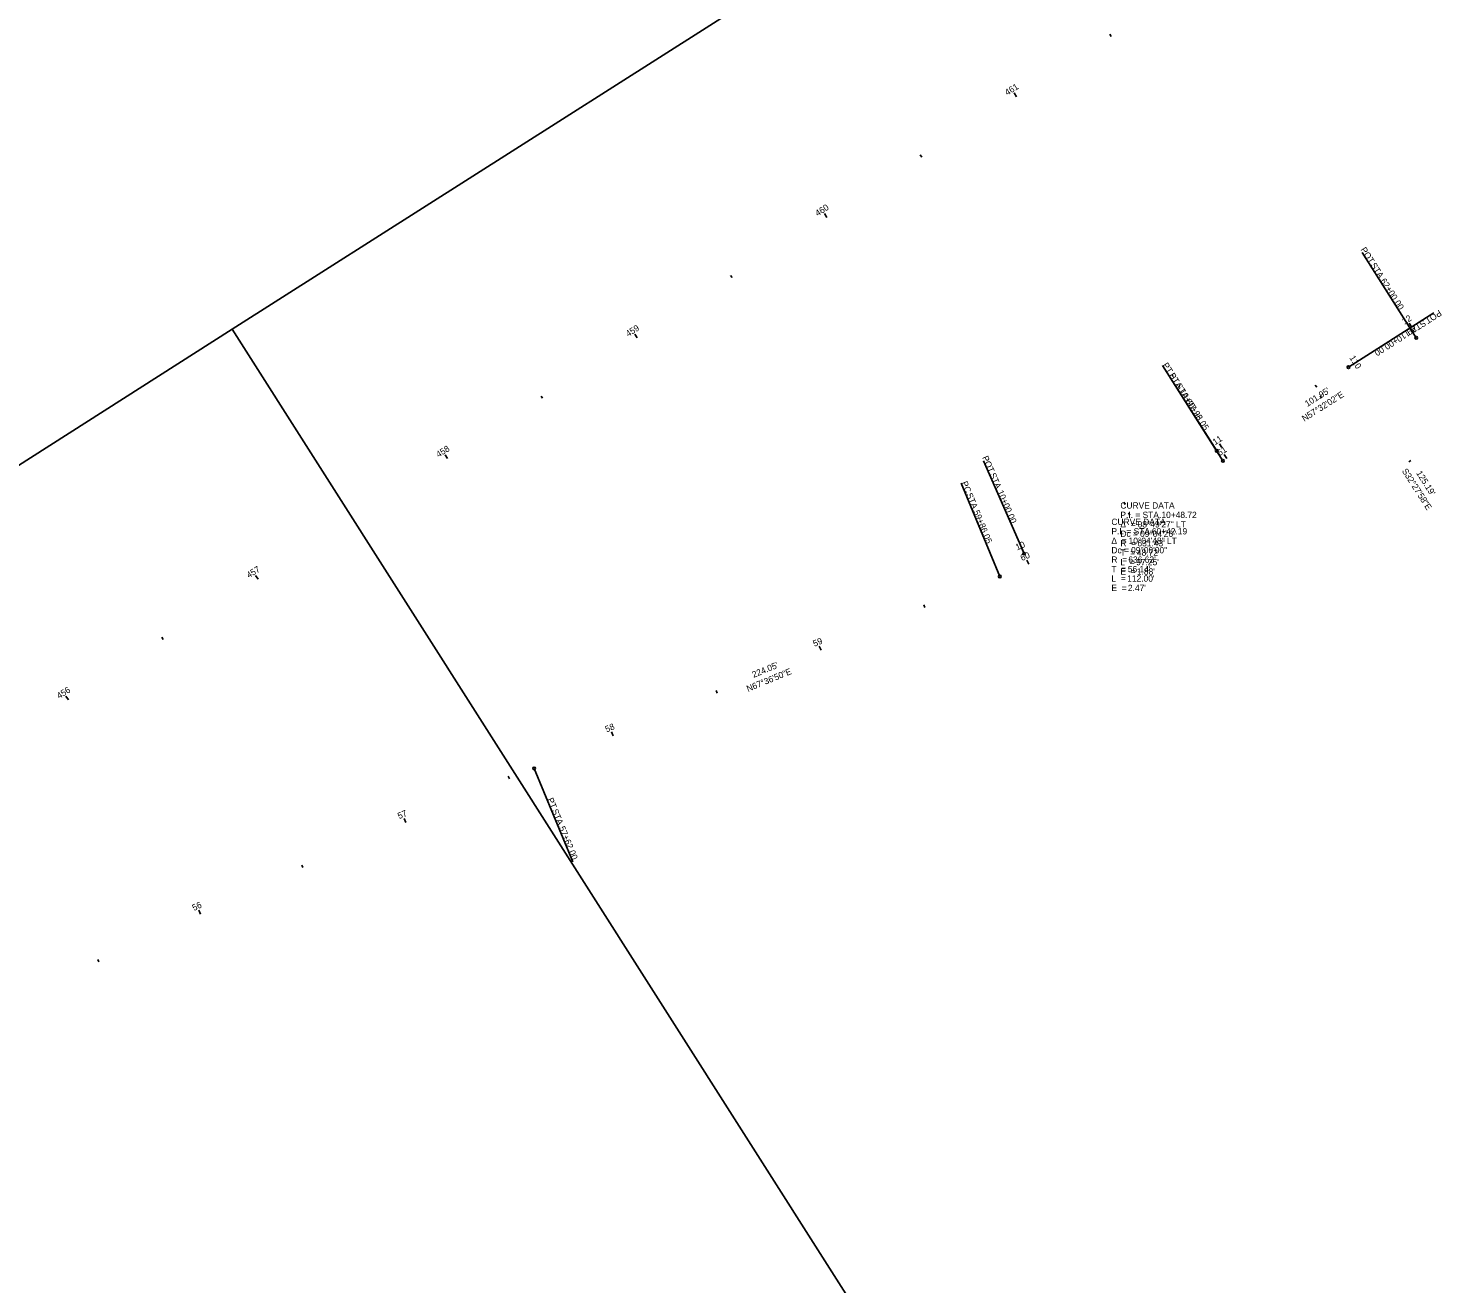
# Model space of a CAD drawing. Extents: x 143421 to 147121, y 511505 to 514560.
# Drawn here: x 144385 to 145019, y 512595 to 513153 of the extents above; entities that cross this region are included whole.
import ezdxf

# ---------------------------------------------------------------- set-up
doc = ezdxf.new("R2010")
doc.units = 0
for name, color, linetype in [('CM_Corridor_Conceptual', 7, 'Continuous'), ('CM_Corridor_Range_Conceptual', 7, 'Continuous'), ('CM_Corridor_Top_Mesh', 7, 'Continuous'), ('DR_P_Sediment_Basin', 7, 'Continuous'), ('DR_Pond', 7, 'Continuous'), ('DT_P_Tie', 7, 'Continuous'), ('DT_X_Contour_Major', 7, 'Continuous'), ('DT_X_Triangles', 7, 'Continuous'), ('MD_P_Surface_Finished_Grade', 7, 'Continuous'), ('PF_X_Ground_Line', 7, 'Continuous'), ('SC_Scratch1', 7, 'Continuous'), ('SC_Scratch2', 7, 'Continuous')]:
    doc.layers.add(name, color=color, linetype=linetype)

msp = doc.modelspace()

# ---------------------------------------------------------------- linework, layer by layer
at = {"layer": 'CM_Corridor_Conceptual'}
for p, q in [((145002.01, 513015.81), (145000.94, 513017.5)), ((144959.83, 512988.97), (144959.18, 512989.99)), ((144917.64, 512962.13), (144916.57, 512963.82)), ((144874.52, 512936.85), (144873.96, 512937.9)), ((144829.55, 512915.02), (144828.75, 512916.85)), ((144783.38, 512895.83), (144782.92, 512896.94)), ((144737.15, 512876.79), (144736.39, 512878.64)), ((144690.92, 512857.75), (144690.46, 512858.86)), ((144644.68, 512838.71), (144643.92, 512840.56)), ((144598.46, 512819.65), (144598, 512820.76)), ((144552.41, 512800.16), (144551.62, 512801.99)), ((144506.63, 512780.07), (144506.14, 512781.16)), ((144461.11, 512759.38), (144460.27, 512761.2)), ((144415.87, 512738.1), (144415.35, 512739.18))]:
    msp.add_line(p, q, dxfattribs=at)
at = {"layer": 'DR_Pond'}
for points in [[(144475.14, 513019.58), (145011.95, 512175.87), (145117.41, 512242.97), (145222.87, 512310.07), (145328.34, 512377.17), (145433.8, 512444.27), (145539.26, 512511.37), (145644.73, 512578.47), (145750.19, 512645.57), (145855.65, 512712.67), (145961.12, 512779.77), (146066.58, 512846.87), (145529.78, 513690.58), (145424.32, 513623.48), (145318.85, 513556.38), (145213.39, 513489.28), (145107.93, 513422.18), (145002.46, 513355.08), (144897, 513287.98), (144791.53, 513220.88), (144686.07, 513153.78), (144580.61, 513086.68)], [(143420.51, 512348.57), (143957.31, 511504.87), (144062.77, 511571.97), (144168.24, 511639.07), (144273.7, 511706.17), (144379.16, 511773.27), (144484.63, 511840.37), (144590.09, 511907.47), (144695.55, 511974.57), (144801.02, 512041.67), (144906.48, 512108.77), (145011.95, 512175.87), (144475.14, 513019.58), (144369.68, 512952.48), (144264.22, 512885.38), (144158.75, 512818.28), (144053.29, 512751.18), (143947.83, 512684.08), (143842.36, 512616.98), (143736.9, 512549.88), (143631.44, 512482.77), (143525.97, 512415.67)]]:
    msp.add_lwpolyline(points, close=True, dxfattribs=at)
at = {"layer": 'DT_P_Tie'}
for p, q in [((144971.8, 513002.75), (145009.77, 513026.9)), ((144913.21, 512965.47), (144889.05, 513003.43)), ((144827.47, 512919.78), (144809.42, 512961))]:
    msp.add_line(p, q, dxfattribs=at)
for centre in [(144971.8, 513002.75), (144913.21, 512965.47), (144827.47, 512919.78)]:
    msp.add_circle(centre, 0.6, dxfattribs=at)
at = {"layer": 'DT_X_Contour_Major'}
for p, q in [((144866.31, 513149.93), (144865.66, 513150.94)), ((144824.12, 513123.09), (144823.05, 513124.77)), ((144781.94, 513096.25), (144781.29, 513097.26)), ((144739.75, 513069.41), (144738.68, 513071.09)), ((144697.57, 513042.57), (144696.92, 513043.58)), ((144655.38, 513015.73), (144654.31, 513017.41)), ((144613.19, 512988.89), (144612.55, 512989.9)), ((144571.01, 512962.05), (144569.94, 512963.73)), ((144528.82, 512935.21), (144528.18, 512936.22)), ((144486.64, 512908.37), (144485.56, 512910.05)), ((144444.45, 512881.53), (144443.81, 512882.54)), ((144402.27, 512854.69), (144401.19, 512856.37))]:
    msp.add_line(p, q, dxfattribs=at)
at = {"layer": 'DT_X_Triangles'}
for p, q in [((144999.9, 513020.62), (144998.83, 513022.31)), ((144971.8, 513002.75), (144973.49, 513003.82)), ((144957.71, 512993.78), (144957.07, 512994.8)), ((144915.53, 512966.94), (144914.46, 512968.63)), ((144998.64, 512960.56), (144999.65, 512961.2)), ((144872.43, 512941.62), (144871.87, 512942.68)), ((144827.47, 512919.78), (144826.67, 512921.61))]:
    msp.add_line(p, q, dxfattribs=at)
at = {"layer": 'SC_Scratch2'}
for p, q in [((145002.01, 513015.81), (144977.86, 513053.78)), ((144915.99, 512961.08), (144891.84, 512999.05)), ((144816.71, 512909.56), (144799.57, 512951.17)), ((144609.55, 512824.24), (144626.69, 512782.63))]:
    msp.add_line(p, q, dxfattribs=at)
for centre in [(145002.01, 513015.81), (144915.99, 512961.08), (144816.71, 512909.56), (144609.55, 512824.24)]:
    msp.add_circle(centre, 0.6, dxfattribs=at)

# ---------------------------------------------------------------- texts
at = {"layer": 'CM_Corridor_Conceptual'}
for s, rotation, p in [('62', 32.46616, (144998.9, 513016.8)), ('61', 32.46616, (144914.52, 512963.11)), ('60', 23.64203, (144826.58, 512916.45)), ('59', 22.38616, (144734.25, 512878.3)), ('58', 22.38616, (144641.76, 512840.21)), ('57', 23.31617, (144549.47, 512801.61)), ('56', 24.81617, (144458.12, 512760.75))]:
    msp.add_text(s, height=2.8, rotation=rotation, dxfattribs=at).set_placement(p)
at = {"layer": 'CM_Corridor_Range_Conceptual'}
for s, rotation, p in [("101.95'", 32.46616, (144953.55, 512985.02)), ("224.05'", 22.38616, (144707.16, 512864.48))]:
    msp.add_text(s, height=2.8, rotation=rotation, dxfattribs=at).set_placement(p)
at = {"layer": 'CM_Corridor_Top_Mesh'}
msp.add_text("125.19'", height=2.8, rotation=302.46616, dxfattribs=at).set_placement((145001.85, 512955.59))
at = {"layer": 'DR_P_Sediment_Basin'}
for s, p in [('CURVE DATA', (144866.35, 512932.52)), ('P.I. = STA. ', (144866.35, 512928.32)), ('60+42.19', (144884.34, 512928.32)), ('Δ  = ', (144866.35, 512924.12)), ('Dc = ', (144866.35, 512919.92)), ('10°04\'48" LT', (144874, 512924.12)), ('09°00\'00"', (144875.1, 512919.92)), ('R  = ', (144866.35, 512915.72)), ("636.62'", (144873.89, 512915.72)), ('T  = ', (144866.35, 512911.52)), ('L  = ', (144866.35, 512907.32)), ("112.00'", (144873.39, 512907.32)), ("56.14'", (144873.67, 512911.52)), ('E  = ', (144866.35, 512903.12)), ("2.47'", (144873.69, 512903.12))]:
    msp.add_text(s, height=2.8, dxfattribs=at).set_placement(p)
at = {"layer": 'DT_P_Tie'}
for s, rotation, p in [(' STA. ', 212.46616, (145006.08, 513024.5)), ('POT', 212.46616, (145012.15, 513028.37)), ('110+00.00', 212.46616, (144998.1, 513019.43)), ('PT', 302.46616, (144888.95, 513003.66)), (' STA. ', 302.46616, (144891.32, 512999.94)), ('10+97.25', 302.46616, (144896.4, 512991.96)), ('POT', 293.64203, (144808.79, 512962.56)), (' STA. ', 293.64203, (144811.68, 512955.96)), ('10+00.00', 293.64203, (144815.47, 512947.3))]:
    msp.add_text(s, height=2.8, rotation=rotation, dxfattribs=at).set_placement(p)
at = {"layer": 'DT_X_Contour_Major'}
for s, p in [('461', (144820.06, 513123.47)), ('460', (144735.65, 513069.76)), ('459', (144651.32, 513016.1)), ('458', (144566.93, 512962.41)), ('457', (144482.56, 512908.73)), ('456', (144398.18, 512855.05))]:
    msp.add_text(s, height=2.8, rotation=32.46616, dxfattribs=at).set_placement(p)
at = {"layer": 'DT_X_Triangles'}
for s, rotation, p in [('12', 32.46616, (144996.73, 513021.57)), ('110', 302.46616, (144972.11, 513006.91)), ('11', 32.46616, (144912.47, 512967.96)), ('10', 23.64203, (144824.43, 512921.17))]:
    msp.add_text(s, height=2.8, rotation=rotation, dxfattribs=at).set_placement(p)
at = {"layer": 'MD_P_Surface_Finished_Grade'}
for s, p in [('CURVE DATA', (144870.34, 512939.82)), ('Δ  = ', (144870.34, 512931.42)), ('P.I. = STA. ', (144870.34, 512935.62)), ('08°49\'27" LT', (144878.01, 512931.42)), ('10+48.72', (144888.6, 512935.62)), ('Dc = ', (144870.34, 512927.22)), ('09°04\'26"', (144879.08, 512927.22)), ('T  = ', (144870.34, 512918.82)), ('R  = ', (144870.34, 512923.02)), ("48.72'", (144877.68, 512918.82)), ("631.43'", (144877.92, 512923.02)), ('L  = ', (144870.34, 512914.62)), ("97.25'", (144877.38, 512914.62)), ('E  = ', (144870.34, 512910.42)), ("1.88'", (144877.68, 512910.42))]:
    msp.add_text(s, height=2.8, dxfattribs=at).set_placement(p)
at = {"layer": 'PF_X_Ground_Line'}
msp.add_text('S32°27\'58"E', height=2.8, rotation=302.46616, dxfattribs=at).set_placement((144995.48, 512956.58))
at = {"layer": 'SC_Scratch1'}
for s, rotation, p in [('N57°32\'02"E', 32.46616, (144952.2, 512978.43)), ('N67°36\'50"E', 22.38616, (144704.68, 512858.23))]:
    msp.add_text(s, height=2.8, rotation=rotation, dxfattribs=at).set_placement(p)
at = {"layer": 'SC_Scratch2'}
for s, rotation, p in [('POT', 302.46616, (144977.09, 513055.05)), (' STA. ', 302.46616, (144980.92, 513049.04)), ('62+00.00', 302.46616, (144985.92, 513041.17)), ('PT', 302.46616, (144891.85, 512999.1)), (' STA. ', 302.46616, (144894.19, 512995.43)), ('60+98.05', 302.46616, (144899.19, 512987.56)), ('PC', 292.38616, (144799.54, 512951.33)), (' STA. ', 292.38616, (144801.3, 512947.08)), ('59+86.05', 292.38616, (144804.85, 512938.46)), ('PT', 292.38616, (144615.26, 512810.47)), (' STA. ', 292.38616, (144616.92, 512806.44)), ('57+62.00', 292.38616, (144620.47, 512797.82))]:
    msp.add_text(s, height=2.8, rotation=rotation, dxfattribs=at).set_placement(p)

doc.saveas('drawing.dxf')
